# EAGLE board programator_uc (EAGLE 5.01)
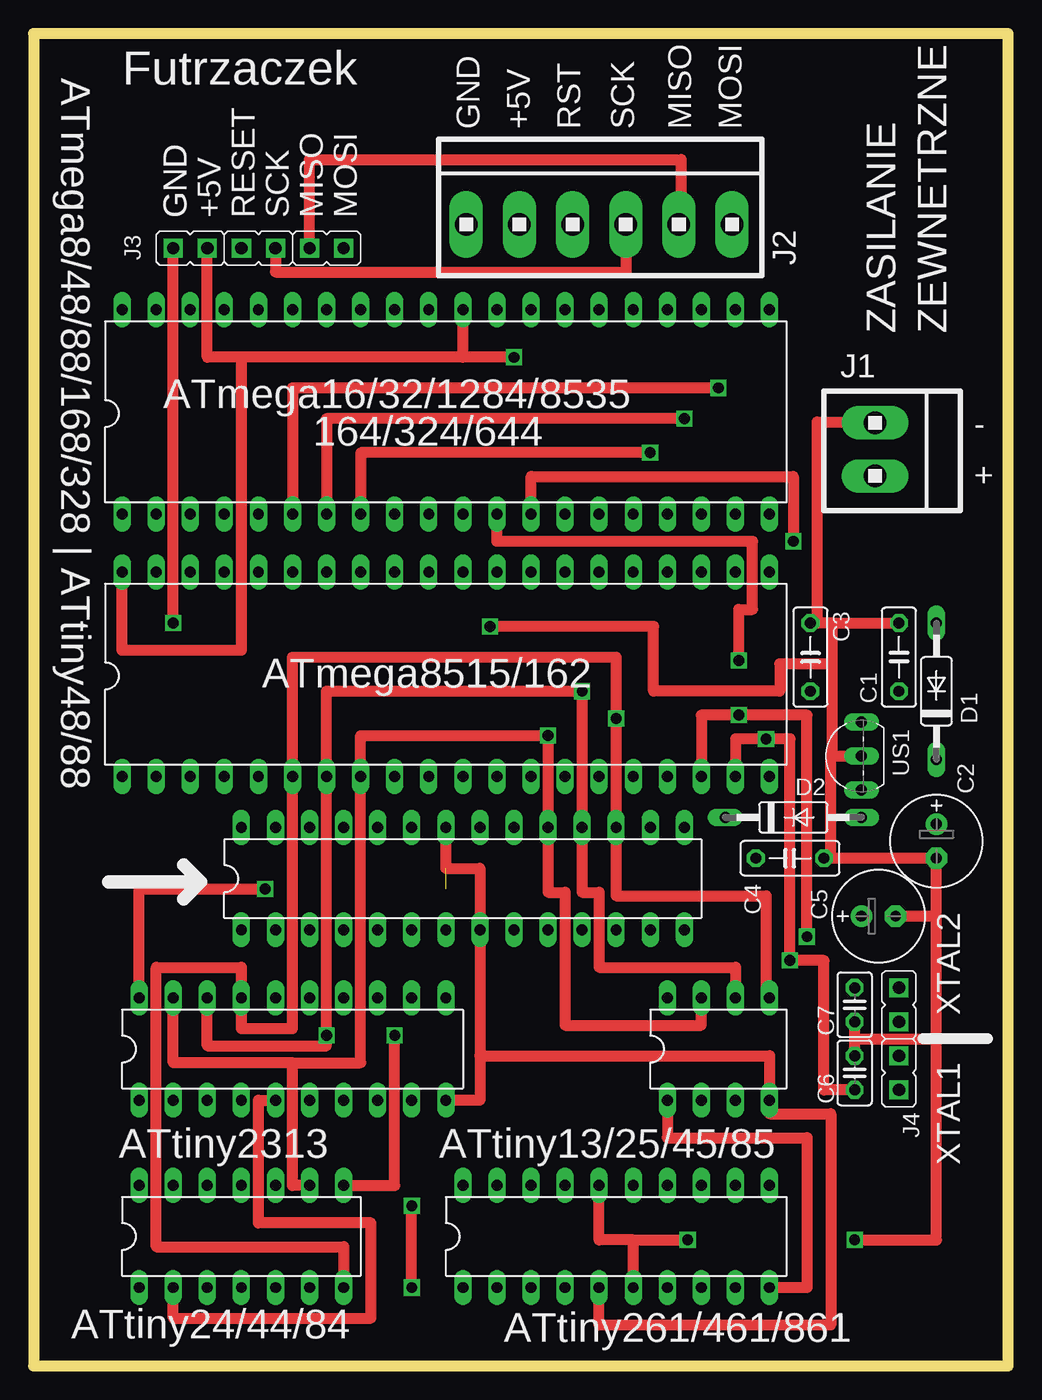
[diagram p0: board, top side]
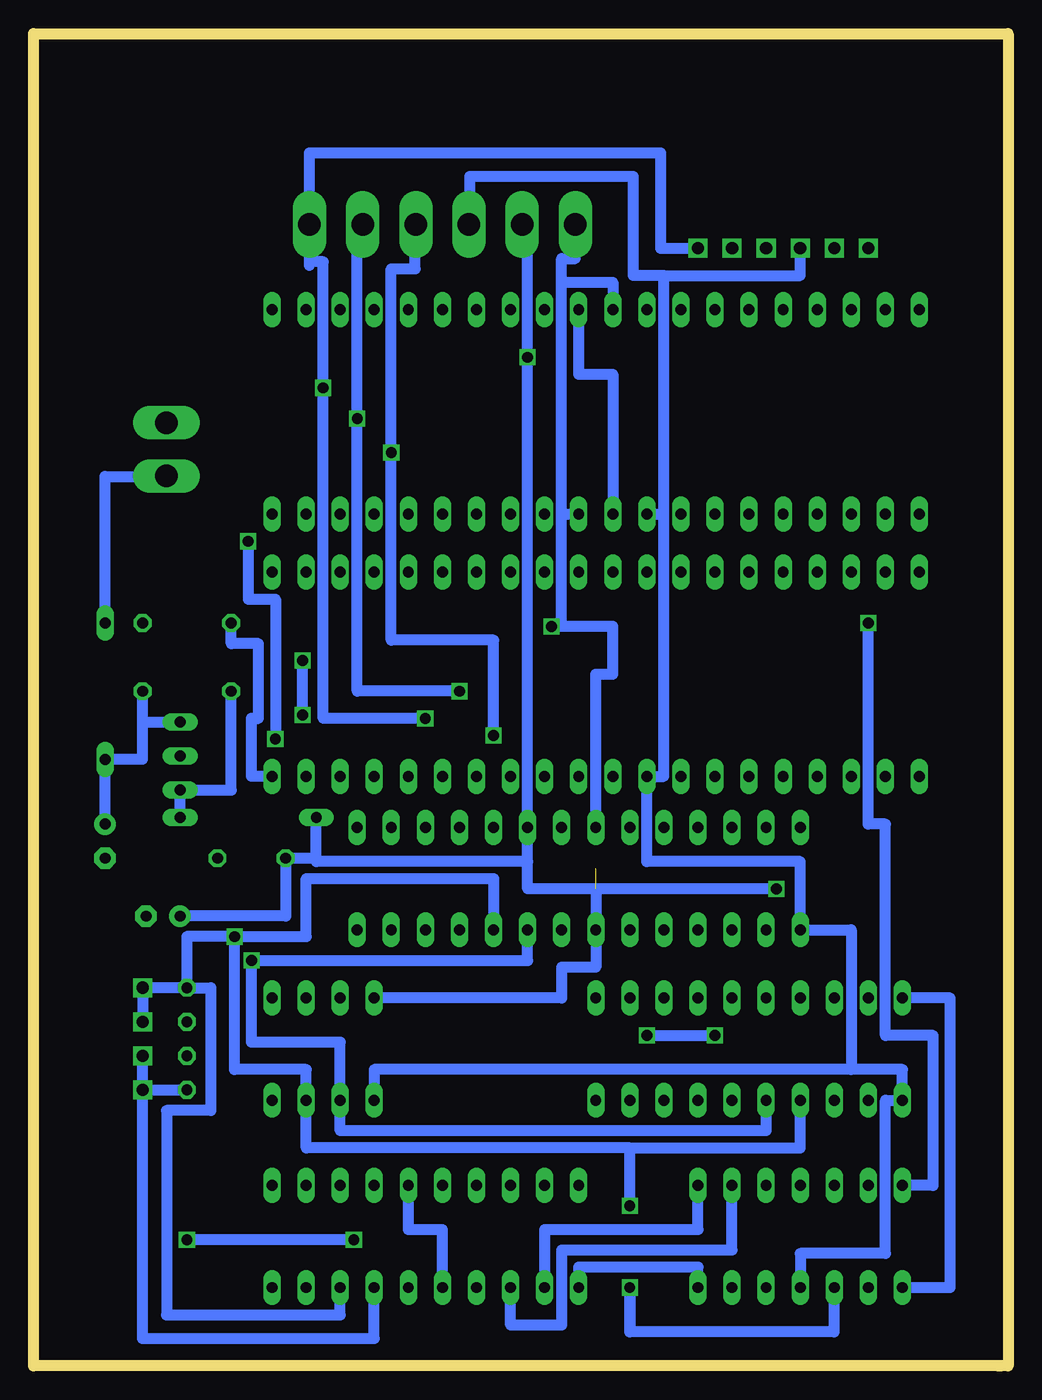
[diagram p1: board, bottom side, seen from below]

Size 72.64 x 99.31 mm. Coordinates in mm from the lower left corner, seen from the top.
Outline: 0.51,0 0.76,0
Outline: 0.76,0 72.64,0 72.64,99.31 0,99.31 0,0 0.76,0
Copper layers (1*16): Top 0.035mm / dielectric 1.5mm / Bottom 0.035mm
Design rules "default": minimum track width 10mil, minimum drill 24mil, track to track 8mil, track to pad 8mil, pad to pad 8mil, via to via 8mil, smd to smd 8mil, copper to edge 40mil, drill to drill 8mil, minimum pad ring 10mil, minimum via ring 8mil, stop-mask expansion 4mil, vias tented up to drill 0mil, thermal gap 10mil

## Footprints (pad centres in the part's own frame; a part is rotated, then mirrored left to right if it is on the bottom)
C050-025X075 = drill 0.813 octagon: 1 -2.54,0; 2 2.54,0
E2,5-7 = drill 0.813 pad 1.6 round: + -1.27,0 | drill 0.813 pad 1.6 octagon: - 1.27,0
C025-025X050 = drill 0.813 octagon: 1 -1.27,0; 2 1.27,0
C2992 = drill 0.813 long: A 5.08,0; C -5.08,0
DIL08 = drill 0.813 long: 1 -3.81,-3.81; 2 -1.27,-3.81; 3 1.27,-3.81; 4 3.81,-3.81; 5 3.81,3.81; 6 1.27,3.81; 7 -1.27,3.81; 8 -3.81,3.81
DIL20 = drill 0.813 long: 1 -11.43,-3.81; 2 -8.89,-3.81; 3 -6.35,-3.81; 4 -3.81,-3.81; 5 -1.27,-3.81; 6 1.27,-3.81; 7 3.81,-3.81; 8 6.35,-3.81; 9 8.89,-3.81; 10 11.43,-3.81; 11 11.43,3.81; 12 8.89,3.81; 13 6.35,3.81; 14 3.81,3.81; 15 1.27,3.81; 16 -1.27,3.81; 17 -3.81,3.81; 18 -6.35,3.81; 19 -8.89,3.81; 20 -11.43,3.81
DIL28-3 = drill 0.813 long: 1 -16.51,-3.81; 2 -13.97,-3.81; 3 -11.43,-3.81; 4 -8.89,-3.81; 5 -6.35,-3.81; 6 -3.81,-3.81; 7 -1.27,-3.81; 8 1.27,-3.81; 9 3.81,-3.81; 10 6.35,-3.81; 11 8.89,-3.81; 12 11.43,-3.81; 13 13.97,-3.81; 14 16.51,-3.81; 15 16.51,3.81; 16 13.97,3.81; 17 11.43,3.81; 18 8.89,3.81; 19 6.35,3.81; 20 3.81,3.81; 21 1.27,3.81; 22 -1.27,3.81; 23 -3.81,3.81; 24 -6.35,3.81; 25 -8.89,3.81; 26 -11.43,3.81; 27 -13.97,3.81; 28 -16.51,3.81
DIL40 = drill 0.813 long: 1 -24.13,-7.62; 2 -21.59,-7.62; 3 -19.05,-7.62; 4 -16.51,-7.62; 5 -13.97,-7.62; 6 -11.43,-7.62; 7 -8.89,-7.62; 8 -6.35,-7.62; 9 -3.81,-7.62; 10 -1.27,-7.62; 11 1.27,-7.62; 12 3.81,-7.62; 13 6.35,-7.62; 14 8.89,-7.62; 15 11.43,-7.62; 16 13.97,-7.62; 17 16.51,-7.62; 18 19.05,-7.62; 19 21.59,-7.62; 20 24.13,-7.62; 21 24.13,7.62; 22 21.59,7.62; 23 19.05,7.62; 24 16.51,7.62; 25 13.97,7.62; 26 11.43,7.62; 27 8.89,7.62; 28 6.35,7.62; 29 3.81,7.62; 30 1.27,7.62; 31 -1.27,7.62; 32 -3.81,7.62; 33 -6.35,7.62; 34 -8.89,7.62; 35 -11.43,7.62; 36 -13.97,7.62; 37 -16.51,7.62; 38 -19.05,7.62; 39 -21.59,7.62; 40 -24.13,7.62
JP1 = drill 0.914 pad 1.422 square: 1 0,-1.27; 2 0,1.27
DIL14 = drill 0.813 long: 1 -7.62,-3.81; 2 -5.08,-3.81; 3 -2.54,-3.81; 4 0,-3.81; 5 2.54,-3.81; 6 5.08,-3.81; 7 7.62,-3.81; 8 7.62,3.81; 9 5.08,3.81; 10 2.54,3.81; 11 0,3.81; 12 -2.54,3.81; 13 -5.08,3.81; 14 -7.62,3.81
1X2MTA = drill 1.676 long: 1 1.981,0; 2 -1.981,0
1X6MTA = drill 1.676 long: 1 9.906,0; 2 5.944,0; 3 1.981,0; 4 -1.981,0; 5 -5.944,0; 6 -9.906,0
TO92- = drill 0.813 long: 1 2.54,0; 2 0,0; 3 -2.54,0

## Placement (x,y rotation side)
C1  [C050-025X075]  64.52,52.83 90 top
C2  [E2,5-7]  67.31,39.12 270 top
C3  [C050-025X075]  57.91,52.83 270 top
C4  [C050-025X075]  56.39,37.85 180 top
C5  [E2,5-7]  62.99,33.53 0 top
C6  [C025-025X050]  61.21,21.84 90 top
C7  [C025-025X050]  61.21,26.92 90 top
D1  [C2992]  67.31,50.29 90 top
D2  [C2992]  56.64,40.89 0 top
E$1  [DIL08]  51.05,23.62 0 top
E$2  [DIL20]  19.3,23.62 0 top
E$3  [DIL28-3]  32,36.32 0 top
E$4  [DIL40]  30.73,51.56 0 top
E$5  [JP1]  11.68,83.31 90 top
E$6  [JP1]  16.76,83.31 90 top
E$7  [DIL40]  30.73,71.12 0 top
E$8  [DIL14]  15.49,9.65 0 top
E$9  [DIL20]  43.43,9.65 0 top
E$10  [JP1]  64.52,26.92 0 top
E$11  [JP1]  64.52,21.84 0 top
J1  [1X2MTA]  62.74,68.33 270 top
J2  [1X6MTA]  42.16,85.09 0 top
J3  [JP1]  21.84,83.31 90 top
US1  [TO92-]  61.72,45.47 90 top

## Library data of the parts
C1-C7 = rcl
D1 D2 = diode
E$1-E$4 E$7-E$9 = 40xx
E$5 E$6 E$10 E$11 J3 = hybrid
J1 J2 = con-amp
US1 = transistor-npn

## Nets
S$1: J3.2
S$2: C3.1 E$4.20
S$3: D1.A
S$4: E$1.1 E$2.1 E$3.1 E$4.9 E$6.2 E$8.4 E$9.10
S$5: E$1.6 E$2.18 E$3.18 E$4.7 E$7.7
S$6: E$7.13
S$7: E$1.5 E$2.17 E$3.17 E$4.6 E$7.6 E$8.7 E$9.1 J2.1 J3.1
S$8: C5.-
S$9: E$1.7 E$2.19 E$3.19 E$4.8 E$8.9 E$9.3
S$11: D1.C US1.1
S$12: E$6.1
S$13: C3.2 D2.A US1.3
S$14: C2.+
S$15: E$7.9
S$16: C6.2 C7.1
S$17: E$1.2 E$2.5 E$3.9 E$8.2
S$18: E$8.14
S$19: E$7.8
S$20: E$8.8 E$9.2
S$21: E$5.2
S$22: C7.2 E$1.3 E$2.4 E$3.10 E$4.18 E$7.12 E$8.3 E$9.8 E$10.1
S$23: C6.1 E$4.19 E$9.7 E$11.2
S$24: C2.- US1.2
S$25: E$9.6 E$9.16
S$26: C5.+ D2.C E$1.4 E$1.8 E$2.10 E$2.20 E$3.7 E$3.8 E$3.20 E$3.22 E$4.40 E$5.1 E$7.10 E$7.11 E$7.30 E$7.31 E$9.5 E$9.15 J2.6

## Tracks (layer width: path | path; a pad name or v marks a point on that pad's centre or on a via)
S$1
  Top 0.813: 48.26,85.09 48.26,89.92 20.57,89.92 J3.2
S$2
  Top 0.813: C3.1 58.17,55.37
  Bottom 0.813: E$4.20 56.39,43.94 56.39,48.26 55.88,48.26 55.88,53.85 57.91,53.85 C3.1
S$3
  Bottom 0.813: 62.74,66.29 67.31,66.29 D1.A
S$4
  Top 0.813: E$9.10 57.66,5.84 57.66,17.02 47.24,17.02 E$1.1
  Bottom 0.813: 40.13,85.34 40.13,88.65 27.94,88.65 27.94,81.28 25.65,81.28 | E$6.2 15.49,81.28 25.65,81.28 | 25.65,81.28 25.65,43.94 E$4.9 26.92,37.59 15.49,37.59 E$3.1 11.68,32.51 11.68,22.1 | E$1.1 47.24,22.1 11.68,22.1 | 11.68,22.1 7.87,22.1 E$2.1 9.14,19.81 9.14,8.38 15.49,8.38 E$8.4
S$5  (via drill 0.8)
  Top 0.813: E$1.6 52.32,29.72 42.16,29.72 42.16,35.31 40.89,35.31 E$3.18 v40.89,50.29 21.84,50.29 E$4.7 21.84,23.88 12.95,23.88 E$2.18 | v48.51,70.61 21.84,70.61 E$7.7
  Bottom 0.813: v40.89,50.29 48.51,50.29 v48.51,70.61 48.51,83.82
S$6  (via drill 0.8)
  Top 0.813: E$7.13 37.08,66.29 56.64,66.29 v56.64,61.47
  Bottom 0.813: v56.64,61.47 56.64,57.15 54.61,57.15 v54.61,46.74
S$7  (via drill 0.8)
  Top 0.813: E$1.5 54.61,27.43 54.61,35.05 43.43,35.05 E$3.17 v43.43,48.26 43.43,52.83 19.3,52.83 E$4.6 19.3,25.15 15.49,25.15 E$2.17 15.49,29.72 9.14,29.72 9.14,8.89 23.11,8.89 E$8.7 | E$7.6 19.3,72.9 v51.05,72.9
  Bottom 0.813: E$9.1 32,7.37 23.11,7.37 E$8.7 | J3.1 25.91,83.31 25.91,90.42 52.07,90.42 52.07,82.04 | 52.07,82.04 J2.1 | 52.07,82.04 52.07,82.3 51.05,82.3 v51.05,72.9 51.05,48.26 v43.43,48.26
S$8
  Top 0.813: C5.- 67.06,33.53
S$9
  Top 0.813: E$1.7 49.78,25.4 39.62,25.4 39.62,35.31 38.35,35.31 E$3.19 38.35,46.99 24.38,46.99 E$4.8 24.38,22.61 19.3,22.61 | 19.3,22.61 10.41,22.61 E$2.19 | E$8.9 19.3,13.46 19.3,22.61
  Bottom 0.813: E$8.9 20.57,8.64 33.27,8.64 33.27,3.05 37.08,3.05 E$9.3
S$10  (via drill 0.8)
  other vias: 38.35,46.99
S$11
  Bottom 0.813: D1.C 64.52,45.21 64.52,48.01 | 64.52,48.01 64.52,50.29 | 64.52,48.01 US1.1
S$12
  Top 0.813: E$6.1 18.03,81.53 44.2,81.53 44.2,84.58
S$13
  Bottom 0.813: D2.A US1.3 57.91,42.93 C3.2
S$14
  Bottom 0.813: C2.+ 67.31,45.21
S$15
  Bottom 0.813: E$7.9 25.91,63.5
S$16
  Top 0.813: 61.21,24.38 C7.1 | 61.21,24.38 67.31,24.38 | C6.2 61.21,24.38
S$17  (via drill 0.8)
  Top 0.813: E$2.5 16.76,19.81 16.76,10.67 25.15,10.67 25.15,3.56 10.41,3.56 E$8.2
  Bottom 0.813: E$3.9 35.81,30.23 v56.39,30.23 56.39,24.13 49.78,24.13 E$1.2 49.78,17.53 18.03,17.53 E$2.5
S$18
  Bottom 0.813: E$8.14 5.59,13.46 5.59,24.64 9.14,24.64 9.14,40.39 10.41,40.39 10.41,55.37
S$19  (via drill 0.8)
  Top 0.813: E$7.8 24.38,68.07 v45.97,68.07
  Bottom 0.813: 44.2,84.58 44.2,81.79 45.97,81.79 v45.97,68.07 45.97,54.1 38.35,54.1 38.35,46.99
S$20  (via drill 0.8)
  Top 0.813: v26.92,24.64 26.92,13.46 E$8.8
  Bottom 0.813: v26.92,24.64 v21.84,24.64 | E$9.2 34.54,10.16 23.11,10.16 E$8.8
S$21  (via drill 0.8)
  Top 0.813: v10.41,55.37 E$5.2
S$22  (via drill 0.8)
  Top 0.813: E$4.18 49.78,48.51 v52.58,48.51 57.66,48.51 v57.66,32 | v28.19,5.84 v28.19,11.94 | v52.58,52.58 52.58,56.39 53.59,56.39 53.59,61.47 34.54,61.47 E$7.12
  Bottom 0.813: E$9.8 49.78,3.81 62.74,3.81 62.74,19.05 59.44,19.05 59.44,28.19 C7.2 | E$10.1 64.52,28.19 C7.2 | E$3.10 38.35,36.32 52.32,36.32 52.32,32 v57.66,32 | v52.58,48.51 v52.58,52.58 | C7.2 61.21,32 v57.66,32 | v57.66,32 57.66,22.1 52.32,22.1 E$1.3 52.32,16.26 28.19,16.26 | E$2.4 15.49,16.26 28.19,16.26 | v28.19,11.94 28.19,16.26 | 28.19,2.79 v28.19,5.84 28.19,2.54 12.95,2.54 E$8.3
S$23
  Top 0.813: E$4.19 52.32,46.74 56.39,46.74 56.39,30.23 58.93,30.23 58.93,20.57 C6.1
  Bottom 0.813: E$9.7 47.24,2.03 64.52,2.03 64.52,20.57 | 64.52,20.57 C6.1 | 64.52,20.57 E$11.2
S$24  (via drill 0.8)
  Top 0.813: 62.74,70.36 58.42,70.36 58.42,55.37 59.56,55.37 | 59.56,55.37 64.52,55.37 | 59.56,55.37 59.56,45.47 59.44,45.47 | 59.44,45.47 US1.2 | 59.44,37.85 59.44,45.47 | 59.44,37.85 58.8,37.85 | 59.44,37.85 C2.- 67.31,9.4 v61.21,9.4
  Bottom 0.813: v48.77,9.4 v61.21,9.4
S$25
  Top 0.813: 44.7,9.4 42.16,9.4 E$9.16 | E$9.6 44.7,9.4 | 44.7,9.4 48.77,9.4
S$26  (via drill 0.8)  (1 unrouted)
  Top 0.813: 59.44,52.32 55.63,52.32 55.63,50.29 46.23,50.29 46.23,55.12 v34.04,55.12 | E$9.5 42.16,3.05 59.44,3.05 59.44,18.8 54.86,18.8 E$1.4 54.86,23.11 33.27,23.11 | E$4.40 6.6,53.34 15.49,53.34 15.49,75.18 | E$5.1 12.95,75.18 15.49,75.18 | E$2.10 33.27,19.81 33.27,23.11 | 32,75.18 15.49,75.18 | 32,75.18 E$7.30 | v35.81,75.18 32,75.18 | 33.27,23.11 E$3.8 33.27,37.08 30.73,37.08 E$3.22 | v17.27,35.56 7.87,35.56 E$2.20
  Bottom 0.813: E$9.15 44.7,10.16 42.16,10.16 E$9.5 | J2.6 32.26,82.55 33.27,82.55 33.27,80.77 | E$7.31 29.46,80.77 33.27,80.77 | E$7.10 29.46,73.91 32,73.91 E$7.30 | 32.26,63.5 E$7.11 33.27,63.5 | 33.27,63.5 33.27,80.77 | C5.+ 53.85,33.53 53.85,37.85 51.56,37.85 | 33.27,55.12 33.27,63.5 | 33.27,55.12 v34.04,55.12 | 33.27,55.12 29.46,55.12 29.46,51.56 30.73,51.56 E$3.22 30.73,41.66 | E$1.8 33.27,27.43 33.27,29.72 30.73,29.72 E$3.7 30.73,35.56 | 35.81,84.33 v35.81,75.18 E$3.20 35.81,37.59 | 51.56,37.85 D2.C | 51.56,37.85 51.56,37.59 35.81,37.59 | 35.81,37.59 35.81,35.56 30.73,35.56 | v17.27,35.56 30.73,35.56 | E$2.20 4.32,27.43 4.32,5.84 7.87,5.84

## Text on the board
tNames: ATmega8/48/88/168/328 | ATtiny48/88 | Futrzaczek | GND | +5V | RST | SCK | MISO | MOSI | GND | GND | +5V | RESET | SCK | MISO | MOSI | ZASILANIE | ZEWNETRZNE | ATmega16/32/1284/8535 | - | 164/324/644 | + | ATmega8515/162 | XTAL2 | J4 | ATtiny2313 | ATtiny13/25/45/85 | XTAL1 | ATtiny24/44/84 | ATtiny261/461/861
